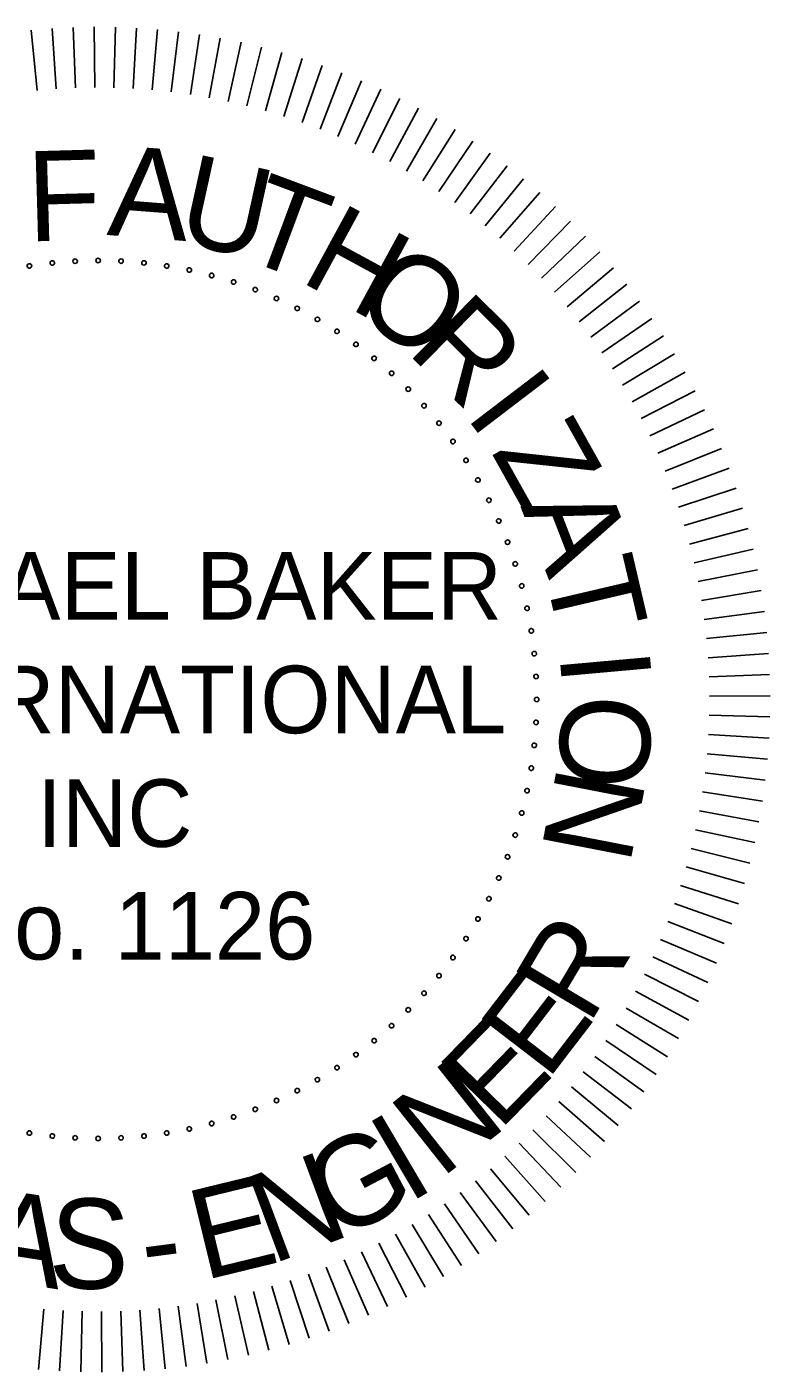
# Model space of a CAD drawing. Extents: x 166 to 3995, y -61 to 2074.
# Drawn here: x 3588.9 to 3726.5, y 250.3 to 499.2 of the extents above; entities that cross this region are included whole.
import ezdxf

# ---------------------------------------------------------------- set-up
doc = ezdxf.new("R2010")
doc.units = 0
doc.layers.add('G-ANNO-TEXT', color=7, linetype='Continuous')

msp = doc.modelspace()

# ---------------------------------------------------------------- linework, layer by layer
at = {"layer": 'G-ANNO-TEXT'}
for points in [[(3590.79, 487.4), (3589.67, 498.57)], [(3589.67, 498.57), (3590.79, 487.4)], [(3594.33, 487.7), (3593.56, 498.9)], [(3593.56, 498.9), (3594.33, 487.7)], [(3597.88, 487.89), (3597.47, 499.1)], [(3597.47, 499.1), (3597.88, 487.89)], [(3601.44, 487.96), (3601.37, 499.19)], [(3601.37, 499.19), (3601.44, 487.96)], [(3604.99, 487.93), (3605.28, 499.15)], [(3605.28, 499.15), (3604.99, 487.93)], [(3608.55, 487.78), (3609.19, 498.98)], [(3609.19, 498.98), (3608.55, 487.78)], [(3612.09, 487.52), (3613.09, 498.7)], [(3613.09, 498.7), (3612.09, 487.52)], [(3615.63, 487.15), (3616.98, 498.29)], [(3616.98, 498.29), (3615.63, 487.15)], [(3619.16, 486.67), (3620.85, 497.76)], [(3620.85, 497.76), (3619.16, 486.67)], [(3622.66, 486.08), (3624.7, 497.11)], [(3624.7, 497.11), (3622.66, 486.08)], [(3626.15, 485.37), (3628.54, 496.34)], [(3628.54, 496.34), (3626.15, 485.37)], [(3629.61, 484.56), (3632.34, 495.45)], [(3632.34, 495.45), (3629.61, 484.56)], [(3633.05, 483.64), (3636.12, 494.44)], [(3636.12, 494.44), (3633.05, 483.64)], [(3636.45, 482.62), (3639.86, 493.31)], [(3639.86, 493.31), (3636.45, 482.62)], [(3639.83, 481.48), (3643.57, 492.06)], [(3643.57, 492.06), (3639.83, 481.48)], [(3643.16, 480.24), (3647.23, 490.7)], [(3647.23, 490.7), (3643.16, 480.24)], [(3646.45, 478.9), (3650.85, 489.23)], [(3650.85, 489.23), (3646.45, 478.9)], [(3649.7, 477.46), (3654.42, 487.64)], [(3654.42, 487.64), (3649.7, 477.46)], [(3652.91, 475.91), (3657.94, 485.94)], [(3657.94, 485.94), (3652.91, 475.91)], [(3656.06, 474.26), (3661.41, 484.13)], [(3661.41, 484.13), (3656.06, 474.26)], [(3659.16, 472.52), (3664.82, 482.21)], [(3664.82, 482.21), (3659.16, 472.52)], [(3662.2, 470.68), (3668.16, 480.18)], [(3668.16, 480.18), (3662.2, 470.68)], [(3665.18, 468.74), (3671.44, 478.06)], [(3671.44, 478.06), (3665.18, 468.74)], [(3668.1, 466.71), (3674.65, 475.83)], [(3674.65, 475.83), (3668.1, 466.71)], [(3670.96, 464.59), (3677.79, 473.5)], [(3677.79, 473.5), (3670.96, 464.59)], [(3673.75, 462.38), (3680.85, 471.07)], [(3680.85, 471.07), (3673.75, 462.38)], [(3676.47, 460.09), (3683.84, 468.55)], [(3683.84, 468.55), (3676.47, 460.09)], [(3686.75, 465.93), (3679.11, 457.71)], [(3679.11, 457.71), (3686.75, 465.93)], [(3689.57, 463.23), (3681.68, 455.25)], [(3681.68, 455.25), (3689.57, 463.23)], [(3692.31, 460.44), (3684.17, 452.71)], [(3684.17, 452.71), (3692.31, 460.44)], [(3694.95, 457.56), (3686.58, 450.09)], [(3686.58, 450.09), (3694.95, 457.56)], [(3697.51, 454.6), (3688.9, 447.4)], [(3688.9, 447.4), (3697.51, 454.6)], [(3699.97, 451.56), (3691.14, 444.64)], [(3691.14, 444.64), (3699.97, 451.56)], [(3702.33, 448.45), (3693.29, 441.8)], [(3693.29, 441.8), (3702.33, 448.45)], [(3704.6, 445.26), (3695.35, 438.9)], [(3695.35, 438.9), (3704.6, 445.26)], [(3706.76, 442.01), (3697.32, 435.94)], [(3697.32, 435.94), (3706.76, 442.01)], [(3708.83, 438.69), (3699.2, 432.92)], [(3699.2, 432.92), (3708.83, 438.69)], [(3710.78, 435.3), (3700.98, 429.84)], [(3700.98, 429.84), (3710.78, 435.3)], [(3712.63, 431.86), (3702.66, 426.71)], [(3702.66, 426.71), (3712.63, 431.86)], [(3714.37, 428.36), (3704.24, 423.52)], [(3704.24, 423.52), (3714.37, 428.36)], [(3716, 424.8), (3705.72, 420.29)], [(3705.72, 420.29), (3716, 424.8)], [(3717.51, 421.2), (3707.1, 417.01)], [(3707.1, 417.01), (3717.51, 421.2)], [(3718.92, 417.55), (3708.38, 413.69)], [(3708.38, 413.69), (3718.92, 417.55)], [(3720.2, 413.86), (3709.55, 410.33)], [(3709.55, 410.33), (3720.2, 413.86)], [(3721.37, 410.13), (3710.61, 406.94)], [(3710.61, 406.94), (3721.37, 410.13)], [(3722.43, 406.36), (3711.57, 403.51)], [(3711.57, 403.51), (3722.43, 406.36)], [(3723.36, 402.57), (3712.42, 400.06)], [(3712.42, 400.06), (3723.36, 402.57)], [(3724.17, 398.74), (3713.16, 396.58)], [(3713.16, 396.58), (3724.17, 398.74)], [(3724.87, 394.9), (3713.79, 393.08)], [(3713.79, 393.08), (3724.87, 394.9)], [(3725.44, 391.03), (3714.31, 389.56)], [(3714.31, 389.56), (3725.44, 391.03)], [(3725.89, 387.15), (3714.72, 386.03)], [(3714.72, 386.03), (3725.89, 387.15)], [(3726.22, 383.25), (3715.02, 382.48)], [(3715.02, 382.48), (3726.22, 383.25)], [(3726.42, 379.35), (3715.21, 378.93)], [(3715.21, 378.93), (3726.42, 379.35)], [(3726.51, 375.44), (3715.28, 375.38)], [(3715.28, 375.38), (3726.51, 375.44)], [(3726.47, 371.53), (3715.25, 371.82)], [(3715.25, 371.82), (3726.47, 371.53)], [(3726.31, 367.62), (3715.1, 368.27)], [(3715.1, 368.27), (3726.31, 367.62)], [(3726.02, 363.73), (3714.84, 364.72)], [(3714.84, 364.72), (3726.02, 363.73)], [(3725.61, 359.84), (3714.47, 361.18)], [(3714.47, 361.18), (3725.61, 359.84)], [(3725.08, 355.96), (3713.99, 357.66)], [(3713.99, 357.66), (3725.08, 355.96)], [(3724.43, 352.11), (3713.4, 354.15)], [(3713.4, 354.15), (3724.43, 352.11)], [(3723.66, 348.28), (3712.7, 350.66)], [(3712.7, 350.66), (3723.66, 348.28)], [(3722.77, 344.47), (3711.88, 347.2)], [(3711.88, 347.2), (3722.77, 344.47)], [(3721.76, 340.69), (3710.97, 343.77)], [(3710.97, 343.77), (3721.76, 340.69)], [(3720.63, 336.95), (3709.94, 340.36)], [(3709.94, 340.36), (3720.63, 336.95)], [(3719.39, 333.25), (3708.81, 336.99)], [(3708.81, 336.99), (3719.39, 333.25)], [(3718.02, 329.58), (3707.57, 333.65)], [(3707.57, 333.65), (3718.02, 329.58)], [(3716.55, 325.96), (3706.22, 330.36)], [(3706.22, 330.36), (3716.55, 325.96)], [(3714.96, 322.39), (3704.78, 327.11)], [(3704.78, 327.11), (3714.96, 322.39)], [(3713.26, 318.87), (3703.23, 323.91)], [(3703.23, 323.91), (3713.26, 318.87)], [(3711.45, 315.4), (3701.58, 320.76)], [(3701.58, 320.76), (3711.45, 315.4)], [(3709.53, 312), (3699.84, 317.66)], [(3699.84, 317.66), (3709.53, 312)], [(3707.51, 308.65), (3698, 314.61)], [(3698, 314.61), (3707.51, 308.65)], [(3705.38, 305.37), (3696.06, 311.63)], [(3696.06, 311.63), (3705.38, 305.37)], [(3703.15, 302.16), (3694.03, 308.71)], [(3694.03, 308.71), (3703.15, 302.16)], [(3700.82, 299.02), (3691.91, 305.85)], [(3691.91, 305.85), (3700.82, 299.02)], [(3698.39, 295.96), (3689.71, 303.06)], [(3689.71, 303.06), (3698.39, 295.96)], [(3695.87, 292.97), (3687.41, 300.35)], [(3687.41, 300.35), (3695.87, 292.97)], [(3693.26, 290.07), (3685.03, 297.7)], [(3685.03, 297.7), (3693.26, 290.07)], [(3690.55, 287.24), (3682.57, 295.14)], [(3682.57, 295.14), (3690.55, 287.24)], [(3687.76, 284.51), (3680.03, 292.65)], [(3680.03, 292.65), (3687.76, 284.51)], [(3684.88, 281.86), (3677.41, 290.24)], [(3677.41, 290.24), (3684.88, 281.86)], [(3681.92, 279.31), (3674.72, 287.91)], [(3674.72, 287.91), (3681.92, 279.31)], [(3678.89, 276.84), (3671.96, 285.67)], [(3671.96, 285.67), (3678.89, 276.84)], [(3672.59, 272.21), (3666.23, 281.46)], [(3666.23, 281.46), (3672.59, 272.21)], [(3675.77, 274.48), (3669.13, 283.52)], [(3669.13, 283.52), (3675.77, 274.48)], [(3669.33, 270.05), (3663.27, 279.49)], [(3663.27, 279.49), (3669.33, 270.05)], [(3666.01, 267.99), (3660.24, 277.62)], [(3660.24, 277.62), (3666.01, 267.99)], [(3659.18, 264.18), (3654.03, 274.16)], [(3654.03, 274.16), (3659.18, 264.18)], [(3662.62, 266.03), (3657.16, 275.84)], [(3657.16, 275.84), (3662.62, 266.03)], [(3655.68, 262.44), (3650.84, 272.57)], [(3650.84, 272.57), (3655.68, 262.44)], [(3648.52, 259.3), (3644.33, 269.71)], [(3644.33, 269.71), (3648.52, 259.3)], [(3652.13, 260.82), (3647.61, 271.09)], [(3647.61, 271.09), (3652.13, 260.82)], [(3641.18, 256.61), (3637.65, 267.27)], [(3637.65, 267.27), (3641.18, 256.61)], [(3644.87, 257.9), (3641.01, 268.44)], [(3641.01, 268.44), (3644.87, 257.9)], [(3629.89, 253.45), (3627.38, 264.39)], [(3627.38, 264.39), (3629.89, 253.45)], [(3633.69, 254.39), (3630.83, 265.24)], [(3630.83, 265.24), (3633.69, 254.39)], [(3637.45, 255.44), (3634.26, 266.2)], [(3634.26, 266.2), (3637.45, 255.44)], [(3591.05, 250.79), (3592.04, 261.97)], [(3592.04, 261.97), (3591.05, 250.79)], [(3594.95, 250.51), (3595.59, 261.71)], [(3595.59, 261.71), (3594.95, 250.51)], [(3598.85, 250.35), (3599.14, 261.56)], [(3599.14, 261.56), (3598.85, 250.35)], [(3602.76, 250.31), (3602.7, 261.53)], [(3602.7, 261.53), (3602.76, 250.31)], [(3606.67, 250.39), (3606.25, 261.6)], [(3606.25, 261.6), (3606.67, 250.39)], [(3610.57, 250.6), (3609.81, 261.79)], [(3609.81, 261.79), (3610.57, 250.6)], [(3614.47, 250.92), (3613.35, 262.09)], [(3613.35, 262.09), (3614.47, 250.92)], [(3618.35, 251.37), (3616.88, 262.5)], [(3616.88, 262.5), (3618.35, 251.37)], [(3622.22, 251.95), (3620.4, 263.02)], [(3620.4, 263.02), (3622.22, 251.95)], [(3626.07, 252.64), (3623.9, 263.65)], [(3623.9, 263.65), (3626.07, 252.64)]]:
    msp.add_lwpolyline(points, dxfattribs=at)
for centre, start, end in [((3593.58, 455.52), 6, 186), ((3593.58, 455.52), 186, 6), ((3597.82, 455.85), 3, 183), ((3597.82, 455.85), 183, 3), ((3602.07, 455.96), 0, 180), ((3602.07, 455.96), 180, 0), ((3606.32, 455.85), 357, 177), ((3606.32, 455.85), 177, 357), ((3610.56, 455.52), 354, 174), ((3610.56, 455.52), 174, 354), ((3589.36, 454.96), 9, 189), ((3589.36, 454.96), 189, 9), ((3614.77, 454.96), 351, 171), ((3614.77, 454.96), 171, 351), ((3618.95, 454.19), 168, 348), ((3618.95, 454.19), 348, 168), ((3623.09, 453.19), 165, 345), ((3623.09, 453.19), 345, 165), ((3627.16, 451.99), 162, 342), ((3627.16, 451.99), 342, 162), ((3631.17, 450.57), 159, 339), ((3631.17, 450.57), 339, 159), ((3635.1, 448.94), 156, 336), ((3635.1, 448.94), 336, 156), ((3638.94, 447.11), 153, 333), ((3638.94, 447.11), 333, 153), ((3642.68, 445.08), 330, 150), ((3642.68, 445.08), 150, 330), ((3646.3, 442.86), 147, 327), ((3646.3, 442.86), 327, 147), ((3649.8, 440.45), 144, 324), ((3649.8, 440.45), 324, 144), ((3653.18, 437.86), 141, 321), ((3653.18, 437.86), 321, 141), ((3656.41, 435.1), 138, 318), ((3656.41, 435.1), 318, 138), ((3659.5, 432.17), 135, 315), ((3659.5, 432.17), 315, 135), ((3662.42, 429.09), 132, 312), ((3662.42, 429.09), 312, 132), ((3665.18, 425.86), 129, 309), ((3665.18, 425.86), 309, 129), ((3667.77, 422.48), 126, 306), ((3667.77, 422.48), 306, 126), ((3670.18, 418.98), 123, 303), ((3670.18, 418.98), 303, 123), ((3672.4, 415.35), 120, 300), ((3672.4, 415.35), 300, 120), ((3674.43, 411.62), 117, 297), ((3674.43, 411.62), 297, 117), ((3676.26, 407.78), 294, 114), ((3676.26, 407.78), 114, 294), ((3677.89, 403.85), 111, 291), ((3677.89, 403.85), 291, 111), ((3679.31, 399.84), 108, 288), ((3679.31, 399.84), 288, 108), ((3680.52, 395.77), 105, 285), ((3680.52, 395.77), 285, 105), ((3681.51, 391.63), 102, 282), ((3681.51, 391.63), 282, 102), ((3682.28, 387.45), 99, 279), ((3682.28, 387.45), 279, 99), ((3682.84, 383.24), 96, 276), ((3682.84, 383.24), 276, 96), ((3683.17, 379), 93, 273), ((3683.17, 379), 273, 93), ((3683.28, 374.75), 90, 270), ((3683.28, 374.75), 270, 90), ((3683.17, 370.5), 87, 267), ((3683.17, 370.5), 267, 87), ((3682.84, 366.26), 84, 264), ((3682.84, 366.26), 264, 84), ((3682.28, 362.04), 81, 261), ((3682.28, 362.04), 261, 81), ((3681.51, 357.86), 78, 258), ((3681.51, 357.86), 258, 78), ((3680.52, 353.73), 75, 255), ((3680.52, 353.73), 255, 75), ((3679.31, 349.65), 72, 252), ((3679.31, 349.65), 252, 72), ((3677.89, 345.64), 69, 249), ((3677.89, 345.64), 249, 69), ((3676.26, 341.71), 66, 246), ((3676.26, 341.71), 246, 66), ((3674.43, 337.88), 63, 243), ((3674.43, 337.88), 243, 63), ((3672.4, 334.14), 60, 240), ((3672.4, 334.14), 240, 60), ((3670.18, 330.51), 57, 237), ((3670.18, 330.51), 237, 57), ((3667.77, 327.01), 54, 234), ((3667.77, 327.01), 234, 54), ((3665.18, 323.64), 51, 231), ((3665.18, 323.64), 231, 51), ((3662.42, 320.4), 48, 228), ((3662.42, 320.4), 228, 48), ((3659.5, 317.32), 45, 225), ((3659.5, 317.32), 225, 45), ((3656.41, 314.39), 42, 222), ((3656.41, 314.39), 222, 42), ((3653.18, 311.63), 39, 219), ((3653.18, 311.63), 219, 39), ((3649.8, 309.04), 36, 216), ((3649.8, 309.04), 216, 36), ((3646.3, 306.63), 33, 213), ((3646.3, 306.63), 213, 33), ((3642.68, 304.41), 30, 210), ((3642.68, 304.41), 210, 30), ((3638.94, 302.38), 27, 207), ((3638.94, 302.38), 207, 27), ((3631.17, 298.93), 21, 201), ((3631.17, 298.93), 201, 21), ((3635.1, 300.55), 24, 204), ((3635.1, 300.55), 204, 24), ((3623.09, 296.3), 15, 195), ((3623.09, 296.3), 195, 15), ((3627.16, 297.51), 18, 198), ((3627.16, 297.51), 198, 18), ((3589.36, 294.53), 351, 171), ((3589.36, 294.53), 171, 351), ((3593.58, 293.98), 354, 174), ((3593.58, 293.98), 174, 354), ((3597.82, 293.64), 357, 177), ((3602.07, 293.53), 0, 180), ((3606.32, 293.64), 3, 183), ((3610.56, 293.98), 6, 186), ((3610.56, 293.98), 186, 6), ((3614.77, 294.53), 9, 189), ((3614.77, 294.53), 189, 9), ((3618.95, 295.31), 12, 192), ((3618.95, 295.31), 192, 12), ((3597.82, 293.64), 177, 357), ((3602.07, 293.53), 180, 0), ((3606.32, 293.64), 183, 3)]:
    msp.add_arc(centre, 0.417, start, end, dxfattribs=at)

# ---------------------------------------------------------------- texts
for s, rotation, p in [('F', 1.5867, (3589.13, 459.48)), ('A', 355.5955, (3603.58, 460.7)), ('U', 347.5481, (3616.2, 459.51)), ('T', 339.5007, (3627.83, 456.73)), ('H', 331.4533, (3639.13, 452.28)), ('O', 323.4059, (3648.7, 447.01)), ('R', 315.3585, (3659.03, 439.1)), ('I', 307.3112, (3669.87, 427.36)), ('Z', 299.2638, (3674.76, 420.57)), ('A', 291.2164, (3680.23, 410.55)), ('T', 283.169, (3684.59, 398.75)), ('I', 275.1216, (3687.48, 383.16)), ('O', 267.0743, (3688.06, 375.99)), ('N', 259.0269, (3687.19, 362.89)), ('R', 59.2262, (3692.93, 314.31)), ('E', 52.4765, (3685.2, 304.04)), ('E', 45.7268, (3676.31, 294.76)), ('N', 38.4196, (3665.54, 285.97)), ('I', 30.5495, (3659.49, 281.38)), ('G', 27.7404, (3646.31, 274.38)), ('N', 20.4332, (3634.18, 270.18)), ('E', 13.6835, (3621.61, 267.24)), ('A', 351.1991, (3580.02, 267.87)), ('S', 357.9489, (3592.73, 266.01)), ('-', 7.5077, (3610.92, 265.97))]:
    msp.add_text(s, height=16.67, rotation=rotation, dxfattribs=at).set_placement(p)
for s, height, p in [('MICHAEL BAKER', 12.5016, (3541.24, 389.52)), (' INTERNATIONAL', 12.5016, (3539.23, 368.5)), ('INC', 12.502, (3590.75, 347.48)), (' No. 1126', 12.502, (3569.8, 326.64))]:
    msp.add_text(s, height=height, dxfattribs=at).set_placement(p)

doc.saveas('drawing.dxf')
